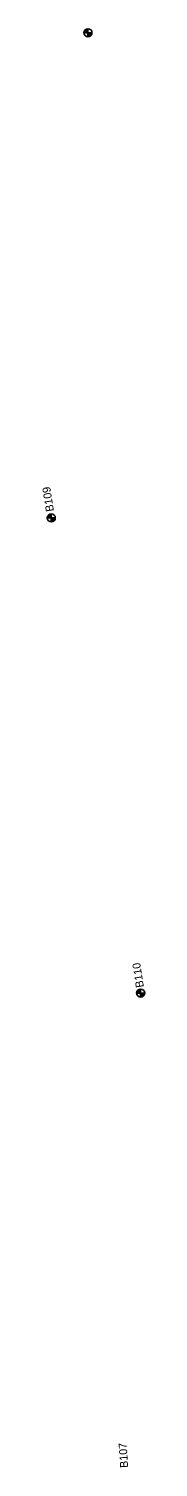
# Model space of a CAD drawing. Extents: x 335726 to 369746, y 119154 to 200788.
# Drawn here: x 355339 to 355467, y 187805 to 189602 of the extents above; entities that cross this region are included whole.
import ezdxf

# ---------------------------------------------------------------- set-up
doc = ezdxf.new("R2010")
doc.units = 0
for name, color, linetype in [('E_SOIL_BORE1 [KAPUR_CADDS_LEVELS]', 7, 'Continuous'), ('E_SOIL_BORE2 [KAPUR_CADDS_LEVELS]', 7, 'Continuous'), ('P_MARK', 7, 'Continuous')]:
    doc.layers.add(name, color=color, linetype=linetype)

msp = doc.modelspace()

# ---------------------------------------------------------------- linework, layer by layer
at = {"layer": 'P_MARK'}
for p, q in [((355390.7, 189597.1), (355400.7, 189597.1)), ((355395.7, 189602.1), (355395.7, 189592.1)), ((355344.9, 188991.1), (355354.9, 188991.1)), ((355349.9, 188996.1), (355349.9, 188986.1)), ((355456.5, 188397.5), (355466.5, 188397.5)), ((355461.5, 188402.5), (355461.5, 188392.5))]:
    msp.add_line(p, q, dxfattribs=at)
for centre in [(355395.7, 189597.1), (355349.9, 188991.1), (355461.5, 188397.5)]:
    msp.add_circle(centre, 5, dxfattribs=at)
for centre, radius, start, end in [((355395.7, 189597.1), 4.5, 89.9869, 179.9869), ((355395.7, 189597.1), 4, 89.9869, 179.9869), ((355395.7, 189597.1), 3.5, 89.9869, 179.9869), ((355395.7, 189597.1), 3, 89.9869, 179.9869), ((355395.7, 189597.1), 2.5, 89.9869, 179.9869), ((355395.7, 189597.1), 2, 89.9869, 179.9869), ((355395.7, 189597.1), 1.5, 89.9869, 179.9869), ((355395.7, 189597.1), 1, 89.9869, 179.9869), ((355395.7, 189597.1), 0.5, 89.9869, 179.9869), ((355395.7, 189597.1), 4.5, 269.9869, 359.9869), ((355395.7, 189597.1), 4, 269.9869, 359.9869), ((355395.7, 189597.1), 3.5, 269.9869, 359.9869), ((355395.7, 189597.1), 3, 269.9869, 359.9869), ((355395.7, 189597.1), 2.5, 269.9869, 359.9869), ((355395.7, 189597.1), 2, 269.9869, 359.9869), ((355395.7, 189597.1), 1.5, 269.9869, 359.9869), ((355395.7, 189597.1), 1, 269.9869, 359.9869), ((355395.7, 189597.1), 0.5, 269.9869, 359.9869), ((355349.9, 188991.1), 4.5, 89.9869, 179.9869), ((355349.9, 188991.1), 4, 89.9869, 179.9869), ((355349.9, 188991.1), 3.5, 89.9869, 179.9869), ((355349.9, 188991.1), 3, 89.9869, 179.9869), ((355349.9, 188991.1), 2.5, 89.9869, 179.9869), ((355349.9, 188991.1), 2, 89.9869, 179.9869), ((355349.9, 188991.1), 1.5, 89.9869, 179.9869), ((355349.9, 188991.1), 1, 89.9869, 179.9869), ((355349.9, 188991.1), 0.5, 89.9869, 179.9869), ((355349.9, 188991.1), 4.5, 269.9869, 359.9869), ((355349.9, 188991.1), 4, 269.9869, 359.9869), ((355349.9, 188991.1), 3.5, 269.9869, 359.9869), ((355349.9, 188991.1), 3, 269.9869, 359.9869), ((355349.9, 188991.1), 2.5, 269.9869, 359.9869), ((355349.9, 188991.1), 2, 269.9869, 359.9869), ((355349.9, 188991.1), 1.5, 269.9869, 359.9869), ((355349.9, 188991.1), 1, 269.9869, 359.9869), ((355349.9, 188991.1), 0.5, 269.9869, 359.9869), ((355461.5, 188397.5), 4.5, 89.9869, 179.9869), ((355461.5, 188397.5), 4, 89.9869, 179.9869), ((355461.5, 188397.5), 3.5, 89.9869, 179.9869), ((355461.5, 188397.5), 3, 89.9869, 179.9869), ((355461.5, 188397.5), 2.5, 89.9869, 179.9869), ((355461.5, 188397.5), 2, 89.9869, 179.9869), ((355461.5, 188397.5), 1.5, 89.9869, 179.9869), ((355461.5, 188397.5), 1, 89.9869, 179.9869), ((355461.5, 188397.5), 0.5, 89.9869, 179.9869), ((355461.5, 188397.5), 4.5, 269.9869, 359.9869), ((355461.5, 188397.5), 4, 269.9869, 359.9869), ((355461.5, 188397.5), 3.5, 269.9869, 359.9869), ((355461.5, 188397.5), 3, 269.9869, 359.9869), ((355461.5, 188397.5), 2.5, 269.9869, 359.9869), ((355461.5, 188397.5), 2, 269.9869, 359.9869), ((355461.5, 188397.5), 1.5, 269.9869, 359.9869), ((355461.5, 188397.5), 1, 269.9869, 359.9869), ((355461.5, 188397.5), 0.5, 269.9869, 359.9869)]:
    msp.add_arc(centre, radius, start, end, dxfattribs=at)

# ---------------------------------------------------------------- texts
at = {"layer": 'E_SOIL_BORE1 [KAPUR_CADDS_LEVELS]'}
msp.add_text('B107', height=10, rotation=93.5868, dxfattribs=at).set_placement((355445.9, 187804.7))
at = {"layer": 'E_SOIL_BORE2 [KAPUR_CADDS_LEVELS]'}
for s, p in [('B109', (355353.2, 188999.7)), ('B110', (355465.6, 188405.1))]:
    msp.add_text(s, height=10, rotation=98.957, dxfattribs=at).set_placement(p)

doc.saveas('drawing.dxf')
